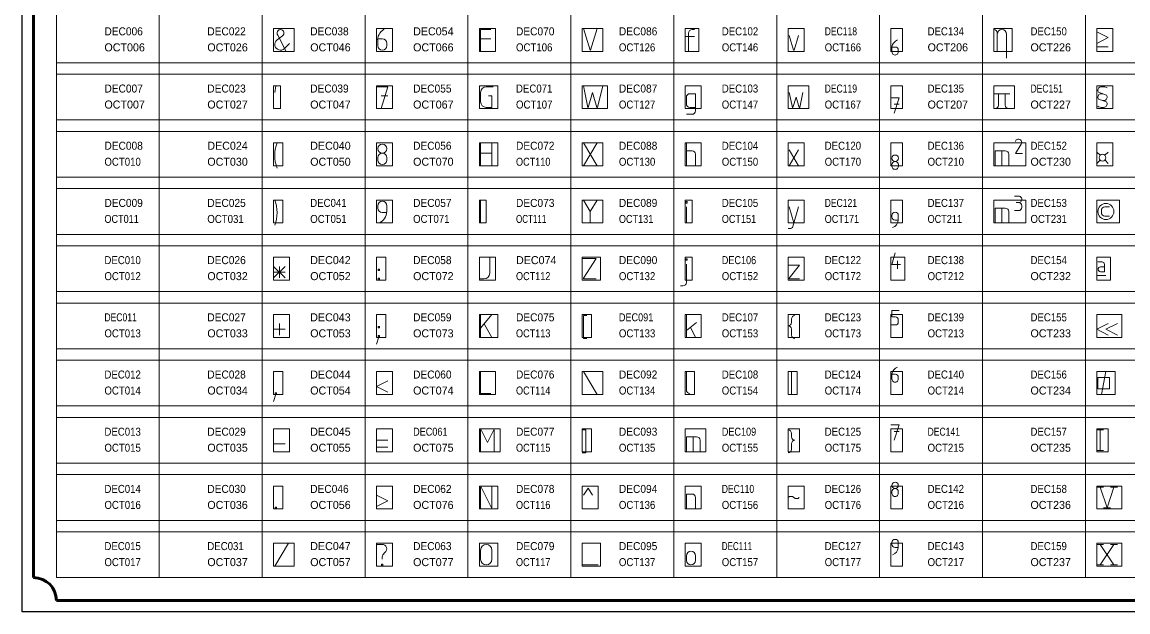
# Model space of a CAD drawing. Extents: x -200 to 7300, y -200 to 4800.
# Drawn here: x -200 to 4636, y -200 to 2378 of the extents above; entities that cross this region are included whole.
import ezdxf

# ---------------------------------------------------------------- set-up
doc = ezdxf.new("R2010")
doc.units = 0
doc.header["$LTSCALE"] = 14
for name, color, linetype, lineweight in [('1', 7, 'Continuous', 13), ('5', 7, 'Continuous', 40), ('6', 7, 'Continuous', 13), ('63', 7, 'Continuous', 13)]:
    doc.layers.add(name, color=color, linetype=linetype, lineweight=lineweight)
doc.layers.add('10', color=7, linetype='Continuous')
doc.layers.add('11', color=7, linetype='Continuous')

msp = doc.modelspace()

# ---------------------------------------------------------------- linework, layer by layer
at = {"layer": '1'}
for p, q in [((2715, 2330), (2715, 2250)), ((2740, 2345), (2730, 2345)), ((4065, 2250), (4065, 2330)), ((4105, 2220), (4105, 2325)), ((939, 2318), (915, 2300)), ((955, 2250), (918, 2321)), ((970, 2285), (947.7, 2262.3)), ((1355, 2305), (1375, 2305)), ((1355, 2300), (1355, 2275)), ((1395, 2285), (1395, 2275)), ((1850, 2305), (1805, 2305)), ((2700, 2315), (2740, 2315)), ((3604, 2270), (3604, 2248)), ((3604, 2269), (3618, 2269)), ((3632, 2255), (3632, 2248)), ((4500, 2270), (4550, 2270)), ((905, 2070), (910, 2100)), ((1860, 2095), (1830, 2095)), ((1370, 2055), (1400, 2055)), ((1805, 2070), (1805, 2030)), ((2705, 2020), (2705, 2050)), ((4050, 2065), (4120, 2065)), ((4070, 2065), (4070, 2015)), ((4100, 2065), (4100, 2015)), ((4508, 2071), (4542, 2059)), ((4508, 2041), (4542, 2029)), ((2745, 2005), (2720, 2005)), ((3614, 2019), (3635, 2019)), ((2730, 1975), (2705, 1975)), ((1805, 1850), (1805, 1750)), ((1855, 1850), (1855, 1750)), ((2255, 1850), (2315, 1750)), ((2315, 1850), (2255, 1750)), ((2705, 1850), (2705, 1750)), ((1805, 1805), (1855, 1805)), ((2705, 1815), (2730, 1815)), ((2745, 1800), (2745, 1750)), ((3155, 1820), (3195, 1750)), ((3195, 1820), (3155, 1750)), ((4085, 1815), (4085, 1750)), ((4115, 1800), (4115, 1750)), ((4500, 1810), (4514.4, 1795.6)), ((4550, 1810), (4535.6, 1795.6)), ((1355, 1785), (1355, 1775)), ((1395, 1785), (1395, 1775)), ((3604.2, 1754.9), (3604.2, 1747.9)), ((3632.2, 1754.9), (3632.2, 1747.9)), ((4500, 1760), (4514.4, 1774.4)), ((4550, 1760), (4536, 1775)), ((1805, 1600), (1805, 1500)), ((4158, 1617), (4140, 1617)), ((1355, 1565), (1355, 1575)), ((1395, 1550), (1395, 1575)), ((2285, 1550), (2285, 1500)), ((2705, 1500), (2705, 1570)), ((3155, 1570), (3175, 1500)), ((3195, 1570), (3171, 1485)), ((4085, 1565), (4085, 1500)), ((4115, 1550), (4115, 1500)), ((4158, 1554), (4140, 1554)), ((4158, 1589), (4147, 1589)), ((4172, 1575), (4172, 1568)), ((4520, 1555), (4520, 1545)), ((4555, 1570), (4535, 1570)), ((1395, 1545), (1375, 1545)), ((3604, 1526), (3604, 1533)), ((3632, 1512), (3618, 1512)), ((3632, 1510), (3632, 1533)), ((4535, 1530), (4555, 1530)), ((3157, 1475), (3150, 1475)), ((900, 1260), (950, 1310)), ((900, 1310), (950, 1260)), ((925, 1310), (925, 1260)), ((1845, 1280), (1845, 1350)), ((2705, 1320), (2705, 1240)), ((3628, 1300), (3628, 1335)), ((4505, 1330), (4523, 1330)), ((4516, 1308), (4534, 1308)), ((900, 1285), (950, 1285)), ((4500, 1270), (4540, 1270)), ((1800, 1255), (1820, 1255)), ((2690, 1225), (2680, 1225)), ((1805, 1100), (1805, 1000)), ((1855, 1100), (1805, 1040)), ((2705, 1100), (2705, 1000)), ((2750, 1065), (2705, 1030)), ((3165, 1080), (3165, 1065)), ((3632, 1075), (3632, 1068)), ((900, 1035), (950, 1035)), ((925, 1010), (925, 1060)), ((1821, 1059), (1855, 1000)), ((2745, 1000), (2723, 1044)), ((3165, 1010), (3165, 1035)), ((3600, 1054), (3618, 1054)), ((2315, 750), (2255, 850)), ((2705, 850), (2705, 770)), ((3165, 850), (3165, 750)), ((3604, 840), (3604, 818)), ((3604, 839), (3618, 839)), ((3632, 825), (3632, 818)), ((4520, 750), (4540, 850)), ((3614, 589), (3635, 589)), ((4500, 595), (4530, 595)), ((4515, 595), (4515, 505)), ((900, 535), (950, 535)), ((1350, 550), (1400, 550)), ((2735, 565), (2735, 500)), ((2765, 550), (2765, 500)), ((3165, 580), (3165, 565)), ((3165, 510), (3165, 535)), ((1350, 520), (1400, 520)), ((4500, 505), (4530, 505)), ((4500, 345), (4530, 345)), ((4590, 345), (4560, 345)), ((2745, 300), (2745, 250)), ((3604, 325), (3604, 318)), ((3632, 325), (3632, 318)), ((4530, 255), (4560, 255)), ((905, 0), (965, 100)), ((3604, 96), (3604, 103)), ((3632, 80), (3632, 103)), ((1350, 95), (1375, 95)), ((1384, 56), (1387, 59)), ((1805, 70), (1805, 30)), ((1855, 70), (1855, 30)), ((3632, 82), (3618, 82)), ((4500, 95), (4530, 95)), ((4515, 95), (4575, 5)), ((4575, 95), (4515, 5)), ((4590, 95), (4560, 95)), ((1375, 30), (1375, 39.3)), ((2250, 5), (2320, 5)), ((2705, 45), (2705, 25)), ((2745, 45), (2745, 25)), ((4500, 5), (4530, 5)), ((4560, 5), (4590, 5))]:
    msp.add_line(p, q, dxfattribs=at)
for points in [[(1850, 2345), (1805, 2345), (1805, 2250)], [(2255, 2350), (2284, 2255), (2286, 2255), (2315, 2350)], [(4500, 2335), (4550, 2310), (4500, 2285)], [(3155, 2320), (3174, 2255), (3176, 2255), (3195, 2320)], [(1350, 2095), (1400, 2095), (1370, 2000)], [(2255, 2100), (2274, 2005), (2276, 2005), (2295, 2070), (2314, 2005), (2316, 2005), (2340, 2100)], [(1830, 2005), (1855, 2005), (1855, 2055), (1840, 2055)], [(2720, 2065), (2745, 2065), (2745, 1990)], [(3155, 2070), (3169, 2005), (3171, 2005), (3185, 2050), (3199, 2005), (3201, 2005), (3215, 2070)], [(3600, 2047), (3635, 2047), (3614, 1980)], [(4175, 1804), (4144, 1804), (4169.3, 1844.9)], [(4055, 1750), (4055, 1815), (4100, 1815)], [(2255, 1600), (2285, 1550), (2315, 1600)], [(4055, 1500), (4055, 1565), (4100, 1565)], [(3642, 1318), (3604, 1318), (3618, 1370)], [(2250, 1345), (2310, 1345), (2255, 1259), (2255, 1255), (2310, 1255)], [(3150, 1315), (3200, 1315), (3155, 1259), (3155, 1255), (3200, 1255)], [(4534, 1319), (4534, 1287), (4516, 1287)], [(3635, 1117), (3604, 1117), (3604, 1089), (3618, 1089)], [(2270, 1095), (2255, 1095), (2255, 995), (2270, 995)], [(4550, 1060), (4500, 1035), (4550, 1010)], [(4590, 1060), (4540, 1035), (4590, 1010)], [(1360, 1002), (1357, 1002), (1357, 1008), (1363, 1008), (1363, 1002), (1360, 1002), (1350, 970)], [(1850, 755), (1805, 755), (1805, 850)], [(1400, 810), (1350, 785), (1400, 760)], [(910, 752), (907, 752), (907, 758), (913, 758), (913, 752), (910, 752), (900, 720)], [(1805, 500), (1805, 595), (1807, 595), (1835, 540), (1863, 595), (1865, 595), (1865, 500)], [(2250, 595), (2265, 595), (2265, 495), (2250, 495)], [(3600, 617), (3635, 617), (3614, 550)], [(2705, 500), (2705, 565), (2750, 565)], [(1805, 250), (1805, 345), (1807, 345), (1853, 255), (1855, 255), (1855, 350)], [(2295, 310), (2275, 340), (2255, 310)], [(4515, 345), (4545, 255), (4575, 345)], [(1350, 310), (1400, 285), (1350, 260)], [(2705, 250), (2705, 315), (2730, 315)]]:
    msp.add_lwpolyline(points, dxfattribs=at)
for points in [[(2702, 1587), (2708, 1587), (2708, 1593), (2702, 1593)], [(2702, 1337), (2708, 1337), (2708, 1343), (2702, 1343)], [(1357, 1292), (1363, 1292), (1363, 1298), (1357, 1298)], [(1357, 1252), (1363, 1252), (1363, 1258), (1357, 1258)], [(1357, 1042), (1363, 1042), (1363, 1048), (1357, 1048)], [(4505, 775), (4555, 775), (4555, 825), (4505, 825)], [(907, 252), (913, 252), (913, 258), (907, 258)], [(1372, 2), (1378, 2), (1378, 8), (1372, 8)]]:
    msp.add_lwpolyline(points, close=True, dxfattribs=at)
for centre, radius in [((1375, 1825), 20), ((3618.2, 1782.9), 14), ((4525, 1785), 15), ((4540, 1550), 35), ((3618, 353), 14)]:
    msp.add_circle(centre, radius, dxfattribs=at)
for centre, radius, start, end in [((930, 2330), 15, 306.8699, 217.6896), ((1411.1, 2297.9), 56.2, 112.1027, 177.9132), ((2730, 2330), 15, 90, 180), ((4050, 2330), 15, 0, 90), ((4085, 2325), 20, 0, 180), ((930, 2280), 25, 126.8699, 315), ((1375, 2275), 20, 180, 360), ((1375, 2285), 20, 0, 90), ((3644.3, 2262.3), 41.1, 113.4429, 169.2375), ((3618, 2248), 14, 179.8538, 0.1462), ((3618, 2255), 14, 0, 90), ((1830, 2070), 25, 90, 180), ((4520, 2080), 15, 105.9454, 216.8699), ((2720, 2050), 15, 90, 180), ((4520, 2050), 15, 105.9454, 216.8699), ((4530, 2050), 15, 285.9454, 36.8699), ((1830, 2030), 25, 180, 270), ((2720, 2020), 15, 180, 270), ((2730, 1990), 15, 270, 0), ((4055, 2015), 15, 270, 0), ((4115, 2015), 15, 180, 270), ((4530, 2020), 15, 285.9454, 36.8699), ((1060, 1795), 155.1, 159.2277, 200.7723), ((4157.5, 1852.5), 14, 327.0948, 165.9638), ((1375, 1785), 20, 0, 180), ((2730, 1800), 15, 0, 90), ((4100, 1800), 15, 0, 90), ((1375, 1775), 20, 180, 360), ((3618.2, 1754.9), 14, 0, 180), ((3618.2, 1747.9), 14, 179.8538, 0.1462), ((760, 1545), 155.1, 339.2277, 20.7722), ((4158, 1603), 14, 265.8439, 90.0653), ((1375, 1575), 20, 0, 180), ((1375, 1565), 20, 180, 270), ((1338.9, 1552), 56.2, 292.1027, 357.9132), ((4100, 1550), 15, 0, 90), ((4158, 1575), 14, 0, 90), ((4158, 1568), 14, 270, 360), ((4535, 1555), 15, 90, 180), ((3618, 1533), 14, 0, 180), ((3618, 1526), 14, 180, 270), ((3593.7, 1516.5), 38.9, 290.0491, 350.3397), ((4535, 1545), 15, 180, 270), ((3157.1, 1490), 15, 270, 338.5769), ((4516, 1297.5), 10.5, 90, 270), ((4523, 1319), 10.7, 0, 90), ((1820, 1280), 25, 270, 0), ((2690, 1240), 15, 270, 0), ((3150, 1065), 15, 270, 0), ((3180, 1080), 15, 90, 180), ((3618, 1075), 14, 0, 90), ((3618, 1068), 14, 270, 360), ((3150, 1035), 15, 0, 90), ((3180, 1010), 15, 180, 270), ((3644.3, 832.3), 41.1, 113.4429, 169.2375), ((3618, 825), 14, 0, 90), ((3618, 818), 14, 179.8538, 0.1462), ((2720, 770), 15, 180, 270), ((3150, 580), 15, 0, 90), ((2750, 550), 15, 0, 90), ((3180, 565), 15, 180, 270), ((3180, 535), 15, 90, 180), ((3150, 510), 15, 270, 0), ((3618, 325), 14, 0, 180), ((2730, 300), 15, 0, 90), ((3163, 288), 17, 45, 134.9981), ((3187, 312), 17, 225, 314.9981), ((3618, 318), 14, 179.8538, 0.1462), ((3618, 103), 14, 0, 180), ((1375, 75), 20, 306.8699, 90), ((1395, 39.3), 20, 123.6901, 180), ((1830, 70), 25, 0, 180), ((2725, 45), 20, 0, 180), ((3618, 96), 14, 180, 270), ((3593.7, 86.5), 38.9, 290.0491, 350.3397), ((1830, 30), 25, 180, 360), ((2725, 25), 20, 180, 360)]:
    msp.add_arc(centre, radius, start, end, dxfattribs=at)
for centre, start_param, end_param in [((4525, 2090), 3.141593, 5.175477), ((4525, 2060), 4.712389, 5.175477), ((4525, 2040), 1.570796, 2.083186), ((4525, 2010), 6.283185, 8.366371)]:
    msp.add_ellipse(centre, major_axis=(-20, 0), ratio=0.25, start_param=start_param, end_param=end_param, dxfattribs=at)
at = {"layer": '5', "lineweight": 53}
for p, q in [((-150, -50), (-150, 4650)), ((7150, -150), (-50, -150))]:
    msp.add_line(p, q, dxfattribs=at)
at = {"layer": '5', "lineweight": 25}
msp.add_lwpolyline([(-200, -200), (-200, 4800), (7300, 4800), (7300, -200)], close=True, dxfattribs=at)
at = {"layer": '5', "lineweight": 53}
msp.add_arc((-150, -150), 100, 0, 90, dxfattribs=at)
at = {"layer": '6'}
for p, q in [((-50, 3950), (-50, -50)), ((400, 3950), (400, -50)), ((850, 3950), (850, -50)), ((1300, 3950), (1300, -50)), ((1750, 3950), (1750, -50)), ((2200, 3950), (2200, -50)), ((2650, 3950), (2650, -50)), ((3100, 3950), (3100, -50)), ((3550, 3950), (3550, -50)), ((4000, 3950), (4000, -50)), ((4450, 3950), (4450, -50)), ((-50, 2200), (7150, 2200)), ((-50, 2150), (7150, 2150)), ((-50, 1950), (7150, 1950)), ((-50, 1900), (7150, 1900)), ((-50, 1700), (7150, 1700)), ((-50, 1650), (7150, 1650)), ((-50, 1450), (7150, 1450)), ((-50, 1400), (7150, 1400)), ((-50, 1200), (7150, 1200)), ((-50, 1150), (7150, 1150)), ((-50, 950), (7150, 950)), ((-50, 900), (7150, 900)), ((-50, 700), (7150, 700)), ((-50, 650), (7150, 650)), ((-50, 450), (7150, 450)), ((-50, 400), (7150, 400)), ((-50, 200), (7150, 200)), ((-50, 150), (7150, 150)), ((-50, -50), (7150, -50))]:
    msp.add_line(p, q, dxfattribs=at)
at = {"layer": '63'}
for points in [[(900, 2250), (990, 2250), (990, 2350), (900, 2350)], [(1350, 2250), (1420, 2250), (1420, 2350), (1350, 2350)], [(1800, 2250), (1870, 2250), (1870, 2350), (1800, 2350)], [(2250, 2250), (2340, 2250), (2340, 2350), (2250, 2350)], [(2700, 2250), (2760, 2250), (2760, 2350), (2700, 2350)], [(3150, 2250), (3220, 2250), (3220, 2350), (3150, 2350)], [(3600, 2250), (3650, 2250), (3650, 2350), (3600, 2350)], [(4050, 2250), (4130, 2250), (4130, 2350), (4050, 2350)], [(4500, 2250), (4570, 2250), (4570, 2350), (4500, 2350)], [(900, 2000), (930, 2000), (930, 2100), (900, 2100)], [(1350, 2000), (1420, 2000), (1420, 2100), (1350, 2100)], [(1800, 2000), (1880, 2000), (1880, 2100), (1800, 2100)], [(2250, 2000), (2360, 2000), (2360, 2100), (2250, 2100)], [(2700, 2000), (2770, 2000), (2770, 2100), (2700, 2100)], [(3150, 2000), (3240, 2000), (3240, 2100), (3150, 2100)], [(3600, 2000), (3650, 2000), (3650, 2100), (3600, 2100)], [(4050, 2000), (4140, 2000), (4140, 2100), (4050, 2100)], [(4500, 2000), (4570, 2000), (4570, 2100), (4500, 2100)], [(900, 1750), (940, 1750), (940, 1850), (900, 1850)], [(1350, 1750), (1420, 1750), (1420, 1850), (1350, 1850)], [(1800, 1750), (1880, 1750), (1880, 1850), (1800, 1850)], [(2250, 1750), (2340, 1750), (2340, 1850), (2250, 1850)], [(2700, 1750), (2770, 1750), (2770, 1850), (2700, 1850)], [(3150, 1750), (3220, 1750), (3220, 1850), (3150, 1850)], [(3600, 1750), (3650, 1750), (3650, 1850), (3600, 1850)], [(4050, 1750), (4190, 1750), (4190, 1850), (4050, 1850)], [(4500, 1750), (4570, 1750), (4570, 1850), (4500, 1850)], [(900, 1500), (940, 1500), (940, 1600), (900, 1600)], [(1350, 1500), (1420, 1500), (1420, 1600), (1350, 1600)], [(1800, 1500), (1830, 1500), (1830, 1600), (1800, 1600)], [(2250, 1500), (2340, 1500), (2340, 1600), (2250, 1600)], [(2700, 1500), (2730, 1500), (2730, 1600), (2700, 1600)], [(3150, 1500), (3220, 1500), (3220, 1600), (3150, 1600)], [(3600, 1500), (3650, 1500), (3650, 1600), (3600, 1600)], [(4050, 1500), (4190, 1500), (4190, 1600), (4050, 1600)], [(4500, 1500), (4600, 1500), (4600, 1600), (4500, 1600)], [(900, 1250), (970, 1250), (970, 1350), (900, 1350)], [(1350, 1250), (1390, 1250), (1390, 1350), (1350, 1350)], [(1800, 1250), (1870, 1250), (1870, 1350), (1800, 1350)], [(2250, 1250), (2330, 1250), (2330, 1350), (2250, 1350)], [(2700, 1250), (2730, 1250), (2730, 1350), (2700, 1350)], [(3150, 1250), (3220, 1250), (3220, 1350), (3150, 1350)], [(3600, 1250), (3660, 1250), (3660, 1350), (3600, 1350)], [(4500, 1250), (4560, 1250), (4560, 1350), (4500, 1350)], [(900, 1000), (970, 1000), (970, 1100), (900, 1100)], [(1350, 1000), (1390, 1000), (1390, 1100), (1350, 1100)], [(1800, 1000), (1880, 1000), (1880, 1100), (1800, 1100)], [(2250, 1000), (2290, 1000), (2290, 1100), (2250, 1100)], [(2700, 1000), (2770, 1000), (2770, 1100), (2700, 1100)], [(3150, 1000), (3200, 1000), (3200, 1100), (3150, 1100)], [(3600, 1000), (3650, 1000), (3650, 1100), (3600, 1100)], [(4500, 1000), (4610, 1000), (4610, 1100), (4500, 1100)], [(900, 750), (940, 750), (940, 850), (900, 850)], [(1350, 750), (1420, 750), (1420, 850), (1350, 850)], [(1800, 750), (1870, 750), (1870, 850), (1800, 850)], [(2250, 750), (2340, 750), (2340, 850), (2250, 850)], [(2700, 750), (2740, 750), (2740, 850), (2700, 850)], [(3150, 750), (3190, 750), (3190, 850), (3150, 850)], [(3600, 750), (3650, 750), (3650, 850), (3600, 850)], [(4500, 750), (4580, 750), (4580, 850), (4500, 850)], [(900, 500), (970, 500), (970, 600), (900, 600)], [(1350, 500), (1420, 500), (1420, 600), (1350, 600)], [(1800, 500), (1890, 500), (1890, 600), (1800, 600)], [(2250, 500), (2290, 500), (2290, 600), (2250, 600)], [(2700, 500), (2790, 500), (2790, 600), (2700, 600)], [(3150, 500), (3200, 500), (3200, 600), (3150, 600)], [(3600, 500), (3650, 500), (3650, 600), (3600, 600)], [(4500, 500), (4550, 500), (4550, 600), (4500, 600)], [(900, 250), (940, 250), (940, 350), (900, 350)], [(1350, 250), (1420, 250), (1420, 350), (1350, 350)], [(1800, 250), (1880, 250), (1880, 350), (1800, 350)], [(2250, 250), (2320, 250), (2320, 350), (2250, 350)], [(2700, 250), (2770, 250), (2770, 350), (2700, 350)], [(3150, 250), (3220, 250), (3220, 350), (3150, 350)], [(3600, 250), (3650, 250), (3650, 350), (3600, 350)], [(4500, 250), (4610, 250), (4610, 350), (4500, 350)], [(900, 0), (990, 0), (990, 100), (900, 100)], [(1350, 0), (1420, 0), (1420, 100), (1350, 100)], [(1800, 0), (1880, 0), (1880, 100), (1800, 100)], [(2250, 0), (2330, 0), (2330, 100), (2250, 100)], [(2700, 0), (2770, 0), (2770, 100), (2700, 100)], [(3600, 0), (3650, 0), (3650, 100), (3600, 100)], [(4500, 0), (4610, 0), (4610, 100), (4500, 100)]]:
    msp.add_lwpolyline(points, close=True, dxfattribs=at)

# ---------------------------------------------------------------- texts
at = {"layer": '10'}
for s, width, p in [('DEC006', 0.95, (160, 2320)), ('DEC022', 0.95, (610, 2320)), ('DEC038', 0.95, (1060, 2320)), ('DEC070', 0.95, (1960, 2320)), ('DEC086', 0.95, (2410, 2320)), ('DEC102', 0.9, (2860, 2320)), ('DEC118', 0.8, (3310, 2320)), ('DEC134', 0.9, (3760, 2320)), ('DEC150', 0.9, (4210, 2320)), ('DEC007', 0.95, (160, 2070)), ('DEC023', 0.95, (610, 2070)), ('DEC039', 0.95, (1060, 2070)), ('DEC055', 0.95, (1510, 2070)), ('DEC071', 0.9, (1960, 2070)), ('DEC087', 0.95, (2410, 2070)), ('DEC103', 0.9, (2860, 2070)), ('DEC119', 0.8, (3310, 2070)), ('DEC135', 0.9, (3760, 2070)), ('DEC151', 0.8, (4210, 2070)), ('DEC008', 0.95, (160, 1820)), ('DEC056', 0.95, (1510, 1820)), ('DEC072', 0.95, (1960, 1820)), ('DEC088', 0.95, (2410, 1820)), ('DEC104', 0.9, (2860, 1820)), ('DEC120', 0.9, (3310, 1820)), ('DEC136', 0.9, (3760, 1820)), ('DEC152', 0.9, (4210, 1820)), ('DEC009', 0.95, (160, 1570)), ('DEC025', 0.95, (610, 1570)), ('DEC041', 0.9, (1060, 1570)), ('DEC057', 0.95, (1510, 1570)), ('DEC073', 0.95, (1960, 1570)), ('DEC089', 0.95, (2410, 1570)), ('DEC105', 0.9, (2860, 1570)), ('DEC121', 0.8, (3310, 1570)), ('DEC137', 0.9, (3760, 1570)), ('DEC153', 0.9, (4210, 1570)), ('DEC010', 0.9, (160, 1320)), ('DEC026', 0.95, (610, 1320)), ('DEC058', 0.95, (1510, 1320)), ('DEC090', 0.95, (2410, 1320)), ('DEC106', 0.85, (2860, 1320)), ('DEC122', 0.9, (3310, 1320)), ('DEC138', 0.9, (3760, 1320)), ('DEC154', 0.9, (4210, 1320)), ('DEC011', 0.8, (160, 1070)), ('DEC027', 0.95, (610, 1070)), ('DEC059', 0.95, (1510, 1070)), ('DEC075', 0.95, (1960, 1070)), ('DEC091', 0.85, (2410, 1070)), ('DEC107', 0.9, (2860, 1070)), ('DEC123', 0.9, (3310, 1070)), ('DEC139', 0.9, (3760, 1070)), ('DEC155', 0.9, (4210, 1070)), ('DEC012', 0.9, (160, 820)), ('DEC028', 0.95, (610, 820)), ('DEC060', 0.95, (1510, 820)), ('DEC076', 0.95, (1960, 820)), ('DEC092', 0.95, (2410, 820)), ('DEC108', 0.9, (2860, 820)), ('DEC124', 0.9, (3310, 820)), ('DEC140', 0.9, (3760, 820)), ('DEC156', 0.9, (4210, 820)), ('DEC013', 0.9, (160, 570)), ('DEC029', 0.95, (610, 570)), ('DEC061', 0.85, (1510, 570)), ('DEC077', 0.95, (1960, 570)), ('DEC093', 0.95, (2410, 570)), ('DEC109', 0.85, (2860, 570)), ('DEC125', 0.9, (3310, 570)), ('DEC141', 0.8, (3760, 570)), ('DEC157', 0.9, (4210, 570)), ('DEC014', 0.9, (160, 320)), ('DEC030', 0.95, (610, 320)), ('DEC046', 0.95, (1060, 320)), ('DEC062', 0.95, (1510, 320)), ('DEC078', 0.95, (1960, 320)), ('DEC094', 0.95, (2410, 320)), ('DEC110', 0.8, (2860, 320)), ('DEC126', 0.9, (3310, 320)), ('DEC142', 0.9, (3760, 320)), ('DEC158', 0.9, (4210, 320)), ('DEC015', 0.9, (160, 70)), ('DEC031', 0.9, (610, 70)), ('DEC063', 0.95, (1510, 70)), ('DEC079', 0.95, (1960, 70)), ('DEC095', 0.95, (2410, 70)), ('DEC111', 0.75, (2860, 70)), ('DEC127', 0.9, (3310, 70)), ('DEC143', 0.9, (3760, 70)), ('DEC159', 0.9, (4210, 70))]:
    msp.add_text(s, height=35, dxfattribs=dict(at, width=width)).set_placement(p)
for s, p in [('DEC054', (1510, 2320)), ('DEC024', (610, 1820)), ('DEC040', (1060, 1820)), ('DEC042', (1060, 1320)), ('DEC074', (1960, 1320)), ('DEC043', (1060, 1070)), ('DEC044', (1060, 820)), ('DEC045', (1060, 570)), ('DEC047', (1060, 70))]:
    msp.add_text(s, height=35, dxfattribs=at).set_placement(p)
at = {"layer": '11'}
for s, p in [('OCT006', (160, 2250)), ('OCT026', (610, 2250)), ('OCT046', (1060, 2250)), ('OCT066', (1510, 2250)), ('OCT206', (3760, 2250)), ('OCT226', (4210, 2250)), ('OCT007', (160, 2000)), ('OCT027', (610, 2000)), ('OCT047', (1060, 2000)), ('OCT067', (1510, 2000)), ('OCT207', (3760, 2000)), ('OCT227', (4210, 2000)), ('OCT030', (610, 1750)), ('OCT050', (1060, 1750)), ('OCT070', (1510, 1750)), ('OCT230', (4210, 1750)), ('OCT032', (610, 1250)), ('OCT052', (1060, 1250)), ('OCT072', (1510, 1250)), ('OCT232', (4210, 1250)), ('OCT033', (610, 1000)), ('OCT053', (1060, 1000)), ('OCT073', (1510, 1000)), ('OCT233', (4210, 1000)), ('OCT034', (610, 750)), ('OCT054', (1060, 750)), ('OCT074', (1510, 750)), ('OCT234', (4210, 750)), ('OCT035', (610, 500)), ('OCT055', (1060, 500)), ('OCT075', (1510, 500)), ('OCT235', (4210, 500)), ('OCT036', (610, 250)), ('OCT056', (1060, 250)), ('OCT076', (1510, 250)), ('OCT236', (4210, 250)), ('OCT037', (610, 0)), ('OCT057', (1060, 0)), ('OCT077', (1510, 0)), ('OCT237', (4210, 0))]:
    msp.add_text(s, height=35, dxfattribs=at).set_placement(p)
for s, width, p in [('OCT106', 0.9, (1960, 2250)), ('OCT126', 0.9, (2410, 2250)), ('OCT146', 0.9, (2860, 2250)), ('OCT166', 0.9, (3310, 2250)), ('OCT107', 0.9, (1960, 2000)), ('OCT127', 0.9, (2410, 2000)), ('OCT147', 0.9, (2860, 2000)), ('OCT167', 0.9, (3310, 2000)), ('OCT010', 0.9, (160, 1750)), ('OCT110', 0.85, (1960, 1750)), ('OCT130', 0.9, (2410, 1750)), ('OCT150', 0.9, (2860, 1750)), ('OCT170', 0.9, (3310, 1750)), ('OCT210', 0.9, (3760, 1750)), ('OCT011', 0.85, (160, 1500)), ('OCT031', 0.9, (610, 1500)), ('OCT051', 0.9, (1060, 1500)), ('OCT071', 0.9, (1510, 1500)), ('OCT111', 0.75, (1960, 1500)), ('OCT131', 0.85, (2410, 1500)), ('OCT151', 0.85, (2860, 1500)), ('OCT171', 0.85, (3310, 1500)), ('OCT211', 0.85, (3760, 1500)), ('OCT231', 0.9, (4210, 1500)), ('OCT012', 0.9, (160, 1250)), ('OCT112', 0.85, (1960, 1250)), ('OCT132', 0.9, (2410, 1250)), ('OCT152', 0.9, (2860, 1250)), ('OCT172', 0.9, (3310, 1250)), ('OCT212', 0.9, (3760, 1250)), ('OCT013', 0.9, (160, 1000)), ('OCT113', 0.85, (1960, 1000)), ('OCT133', 0.9, (2410, 1000)), ('OCT153', 0.9, (2860, 1000)), ('OCT173', 0.9, (3310, 1000)), ('OCT213', 0.9, (3760, 1000)), ('OCT014', 0.9, (160, 750)), ('OCT114', 0.85, (1960, 750)), ('OCT134', 0.9, (2410, 750)), ('OCT154', 0.9, (2860, 750)), ('OCT174', 0.9, (3310, 750)), ('OCT214', 0.9, (3760, 750)), ('OCT015', 0.9, (160, 500)), ('OCT115', 0.85, (1960, 500)), ('OCT135', 0.9, (2410, 500)), ('OCT155', 0.9, (2860, 500)), ('OCT175', 0.9, (3310, 500)), ('OCT215', 0.9, (3760, 500)), ('OCT016', 0.9, (160, 250)), ('OCT116', 0.85, (1960, 250)), ('OCT136', 0.9, (2410, 250)), ('OCT156', 0.9, (2860, 250)), ('OCT176', 0.9, (3310, 250)), ('OCT216', 0.9, (3760, 250)), ('OCT017', 0.9, (160, 0)), ('OCT117', 0.85, (1960, 0)), ('OCT137', 0.9, (2410, 0)), ('OCT157', 0.9, (2860, 0)), ('OCT177', 0.9, (3310, 0)), ('OCT217', 0.9, (3760, 0))]:
    msp.add_text(s, height=35, dxfattribs=dict(at, width=width)).set_placement(p)

doc.saveas('drawing.dxf')
